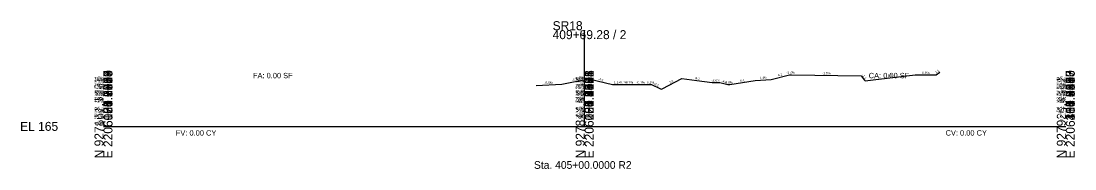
# Model space of a CAD drawing. Extents: x -26 to 2303, y -13 to 9551.
# Drawn here: x 1974.3 to 2302.8, y 7986.7 to 8032.8 of the extents above; entities that cross this region are included whole.
import ezdxf

# ---------------------------------------------------------------- set-up
doc = ezdxf.new("R2010")
doc.units = 0
for name, color, linetype in [('Draft_XS_Grid', 7, 'Continuous'), ('Draft_XS_Text', 7, 'Continuous'), ('DTM_X_GROUND', 7, 'Continuous'), ('XS_CELL', 7, 'Continuous'), ('XS_P_TX_FS_BS', 7, 'Continuous'), ('XS_SHEET_EW_TX_AREA', 7, 'Continuous'), ('XS_SHEET_EW_TX_VOLUME', 7, 'Continuous')]:
    doc.layers.add(name, color=color, linetype=linetype)

msp = doc.modelspace()

# ---------------------------------------------------------------- linework, layer by layer
at = {"layer": 'DTM_X_GROUND'}
msp.add_lwpolyline([(2134.88, 8012.7), (2142.88, 8013.14), (2151.32, 8014.87), (2158.66, 8013.02), (2159.09, 8013.05), (2160.04, 8013.06), (2160.99, 8013.07), (2161.07, 8013.07), (2161.14, 8013.07), (2162.89, 8013.07), (2164.7, 8013.07), (2164.89, 8013.07), (2170.01, 8013.06), (2170.82, 8013.06), (2173.41, 8011.82), (2173.9, 8011.58), (2174.15, 8011.71), (2180.32, 8014.91), (2185, 8014.31), (2189.75, 8013.69), (2192.1, 8013.63), (2192.19, 8013.63), (2194.66, 8013.04), (2195.23, 8013.01), (2203.19, 8014.3), (2208.12, 8014.66), (2213.86, 8016.1), (2214.47, 8016.09), (2236.16, 8015.77), (2237.14, 8014.53), (2237.44, 8014.23), (2239.96, 8014.53), (2253, 8016.08), (2259.6, 8016.02), (2260.75, 8016.93)], dxfattribs=at)
at = {"layer": 'XS_CELL'}
for p, q in [((2150, 8000), (2150, 8030)), ((2150, 8000), (2150, 8030)), ((2150, 8000), (2150, 8030)), ((2150, 8000), (2150, 8030)), ((2150, 8000), (2150, 8030)), ((2150, 8000), (2150, 8030)), ((2150, 8000), (2150, 8030)), ((2150, 8000), (2150, 8030)), ((2150, 8000), (2150, 8030)), ((2150, 8000), (2150, 8030)), ((2150, 8000), (2150, 8030)), ((2000, 8000), (2150, 8000)), ((2000, 8000), (2150, 8000)), ((2000, 8000), (2150, 8000)), ((2000, 8000), (2150, 8000)), ((2000, 8000), (2150, 8000)), ((2000, 8000), (2150, 8000)), ((2000, 8000), (2150, 8000)), ((2000, 8000), (2150, 8000)), ((2000, 8000), (2150, 8000)), ((2000, 8000), (2150, 8000)), ((2000, 8000), (2150, 8000)), ((2150, 8000), (2300, 8000)), ((2150, 8000), (2300, 8000)), ((2150, 8000), (2300, 8000)), ((2150, 8000), (2300, 8000)), ((2150, 8000), (2300, 8000)), ((2150, 8000), (2300, 8000)), ((2150, 8000), (2300, 8000)), ((2150, 8000), (2300, 8000)), ((2150, 8000), (2300, 8000)), ((2150, 8000), (2300, 8000)), ((2150, 8000), (2300, 8000))]:
    msp.add_line(p, q, dxfattribs=at)

# ---------------------------------------------------------------- texts
at = {"layer": 'Draft_XS_Grid'}
msp.add_text('-', height=0.0001, dxfattribs=at).set_placement((2000, 8000))
at = {"layer": 'Draft_XS_Text'}
msp.add_text('Sta. 405+00.0000 R2', height=2.4, dxfattribs=at).set_placement((2134.2, 7986.75))
at = {"layer": 'XS_CELL'}
for s, p in [('SR18', (2140, 8030)), ('SR18', (2140, 8030)), ('SR18', (2140, 8030)), ('SR18', (2140, 8030)), ('SR18', (2140, 8030)), ('SR18', (2140, 8030)), ('SR18', (2140, 8030)), ('SR18', (2140, 8030)), ('SR18', (2140, 8030)), ('SR18', (2140, 8030)), ('SR18', (2140, 8030)), ('405+00.00 / 2', (2140, 8027.2)), ('405+50.00 / 2', (2140, 8027.2)), ('406+00.00 / 2', (2140, 8027.2)), ('406+50.00 / 2', (2140, 8027.2)), ('407+00.00 / 2', (2140, 8027.2)), ('407+50.00 / 2', (2140, 8027.2)), ('408+00.00 / 2', (2140, 8027.2)), ('408+50.00 / 2', (2140, 8027.2)), ('409+00.00 / 2', (2140, 8027.2)), ('409+50.00 / 2', (2140, 8027.2)), ('409+99.28 / 2', (2140, 8027.2)), ('EL 165', (1974, 7998.6)), ('EL 165', (1974, 7998.6)), ('EL 165', (1974, 7998.6)), ('EL 165', (1974, 7998.6)), ('EL 165', (1974, 7998.6)), ('EL 165', (1974, 7998.6)), ('EL 165', (1974, 7998.6)), ('EL 165', (1974, 7998.6)), ('EL 165', (1974, 7998.6)), ('EL 165', (1974, 7998.6)), ('EL 165', (1974, 7998.6))]:
    msp.add_text(s, height=2.8, dxfattribs=at).set_placement(p)
for s, p in [('E 2205900.1434', (2002.8, 7990)), ('E 2205951.6060', (2002.8, 7990)), ('E 2206028.8000', (2002.8, 7990)), ('E 2205977.3373', (2002.8, 7990)), ('E 2206003.0686', (2002.8, 7990)), ('E 2206054.5313', (2002.8, 7990)), ('E 2206080.2626', (2002.8, 7990)), ('E 2206131.7253', (2002.8, 7990)), ('E 2206105.9939', (2002.8, 7990)), ('E 2205925.8747', (2002.8, 7990)), ('E 2206157.0867', (2002.8, 7990)), ('E 2206260.3374', (2152.8, 7990)), ('E 2206028.7555', (2152.8, 7990)), ('E 2206105.9495', (2152.8, 7990)), ('E 2206183.1435', (2152.8, 7990)), ('E 2206054.4868', (2152.8, 7990)), ('E 2206131.6808', (2152.8, 7990)), ('E 2206208.8748', (2152.8, 7990)), ('E 2206285.6988', (2152.8, 7990)), ('E 2206080.2182', (2152.8, 7990)), ('E 2206157.4121', (2152.8, 7990)), ('E 2206234.6061', (2152.8, 7990)), ('E 2206183.0990', (2302.8, 7990)), ('E 2206260.2930', (2302.8, 7990)), ('E 2206337.4870', (2302.8, 7990)), ('E 2206414.3110', (2302.8, 7990)), ('E 2206208.8303', (2302.8, 7990)), ('E 2206286.0243', (2302.8, 7990)), ('E 2206311.7556', (2302.8, 7990)), ('E 2206363.2183', (2302.8, 7990)), ('E 2206388.9496', (2302.8, 7990)), ('E 2206157.3677', (2302.8, 7990)), ('E 2206234.5617', (2302.8, 7990)), ('N 928146.5884', (2000, 7990)), ('N 927889.3640', (2000, 7990)), ('N 927975.1055', (2000, 7990)), ('N 928231.7135', (2000, 7990)), ('N 927803.6226', (2000, 7990)), ('N 927846.4933', (2000, 7990)), ('N 928103.7176', (2000, 7990)), ('N 928060.8469', (2000, 7990)), ('N 928189.4591', (2000, 7990)), ('N 927932.2347', (2000, 7990)), ('N 928017.9762', (2000, 7990)), ('N 928069.3944', (2150, 7990)), ('N 927983.6530', (2150, 7990)), ('N 927855.0408', (2150, 7990)), ('N 927897.9115', (2150, 7990)), ('N 928154.5195', (2150, 7990)), ('N 927726.4286', (2150, 7990)), ('N 927769.2993', (2150, 7990)), ('N 927812.1701', (2150, 7990)), ('N 928112.2651', (2150, 7990)), ('N 927940.7822', (2150, 7990)), ('N 928026.5237', (2150, 7990)), ('N 927692.1054', (2300, 7990)), ('N 927992.2004', (2300, 7990)), ('N 927906.4590', (2300, 7990)), ('N 927777.8468', (2300, 7990)), ('N 927820.7175', (2300, 7990)), ('N 927649.2346', (2300, 7990)), ('N 927863.5883', (2300, 7990)), ('N 928077.3256', (2300, 7990)), ('N 927734.9761', (2300, 7990)), ('N 927949.3297', (2300, 7990)), ('N 928035.0712', (2300, 7990))]:
    msp.add_text(s, height=2.8, rotation=90, dxfattribs=at).set_placement(p)
at = {"layer": 'XS_P_TX_FS_BS'}
for s, rotation, p in [('4:1', 14.0969, (2210.32, 8015.52)), ('-1.4%', 359.1889, (2212.89, 8016.42)), ('-1.5%', 359.155, (2224.04, 8016.25)), ('8:1', 6.7788, (2244.58, 8015.38)), ('-0.9%', 359.4994, (2254.9, 8016.36)), ('1:1', 38.1787, (2259.58, 8016.39)), ('-5.5%', 3.1715, (2137.5, 8013.15)), ('-5:1', 11.5814, (2146.15, 8014.12)), ('-4:1', 345.8607, (2154.18, 8014.46)), ('1.1%', 0.6029, (2159.15, 8013.35)), ('-0.1%', 359.9228, (2160.71, 8013.37)), ('-0.1%', 359.9405, (2162.49, 8013.37)), ('-0.1%', 359.9248, (2166.15, 8013.37)), ('0.1%', 0.0369, (2169.4, 8013.36)), ('-2:1', 334.3237, (2171.42, 8013.1)), ('2:1', 27.4124, (2176.56, 8013.3)), ('-8:1', 352.6015, (2184.17, 8014.71)), ('-2.6%', 358.5064, (2189.55, 8013.99)), ('-4:1', 346.7322, (2192.61, 8013.83)), ('-6.0%', 356.587, (2193.55, 8013.41)), ('6:1', 9.1975, (2198.54, 8013.85)), ('7.4%', 4.2143, (2204.56, 8014.7)), ('-1:1', 308.2476, (2236.38, 8015.98))]:
    msp.add_text(s, height=0.72, rotation=rotation, dxfattribs=at).set_placement(p)
at = {"layer": 'XS_SHEET_EW_TX_AREA'}
for s, p in [('FA: 0.00 SF', (2046.6, 8015)), ('CA: 0.00 SF', (2238.56, 8015))]:
    msp.add_text(s, height=1.68, dxfattribs=at).set_placement(p)
at = {"layer": 'XS_SHEET_EW_TX_VOLUME'}
for s, p in [('FV: 0.00 CY', (2022.55, 7997.12)), ('CV: 0.00 CY', (2262.51, 7997.12))]:
    msp.add_text(s, height=1.68, dxfattribs=at).set_placement(p)

doc.saveas('drawing.dxf')
